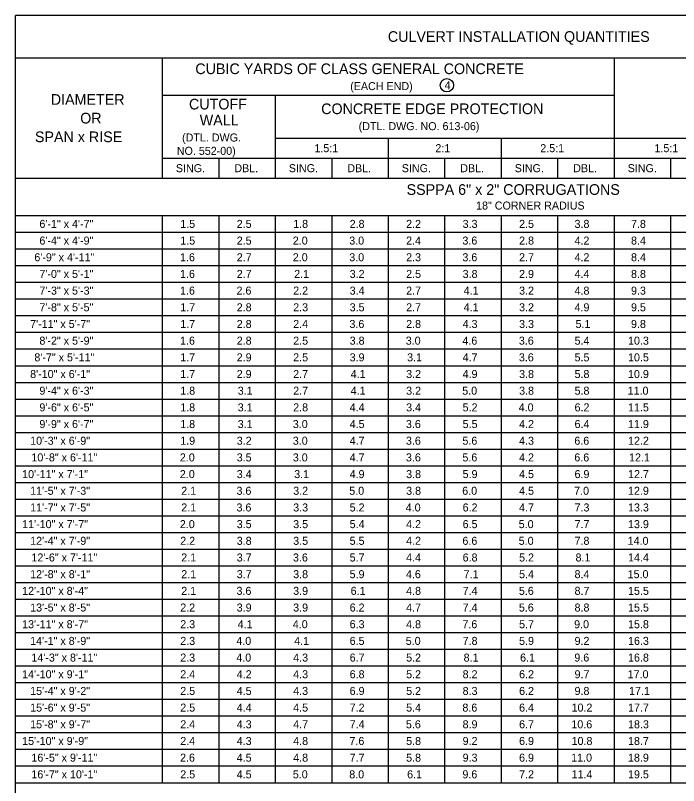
# Model space of a CAD drawing. Extents: x 49991.4 to 50047.6, y 49987.6 to 50011.4.
# Drawn here: x 50031.01 to 50035.98, y 49992.39 to 49998.16 of the extents above; entities that cross this region are included whole.
import ezdxf

# ---------------------------------------------------------------- set-up
doc = ezdxf.new("R2010")
doc.units = 0
doc.layers.add('Level 2', color=7, linetype='Continuous')

msp = doc.modelspace()

# ---------------------------------------------------------------- linework, layer by layer
at = {"layer": 'Level 2'}
for p, q in [((50031.0121, 49989.1307), (50031.0121, 49998.1607)), ((50038.8821, 49998.1607), (50031.0121, 49998.1607)), ((50038.8821, 49997.8407), (50031.0121, 49997.8407)), ((50032.1125, 49997.8407), (50032.1125, 49996.9407)), ((50035.4973, 49997.8407), (50035.4973, 49996.9407)), ((50035.4973, 49997.5607), (50032.1125, 49997.5607)), ((50032.9587, 49997.5607), (50032.9587, 49996.9407)), ((50032.9587, 49997.2407), (50038.0359, 49997.2407)), ((50033.8049, 49997.2407), (50033.8049, 49996.9407)), ((50034.6511, 49997.2407), (50034.6511, 49996.9407)), ((50032.1125, 49997.0907), (50038.8821, 49997.0907)), ((50032.5356, 49997.0907), (50032.5356, 49996.9407)), ((50033.3818, 49997.0907), (50033.3818, 49996.9407)), ((50034.228, 49997.0907), (50034.228, 49996.9407)), ((50035.0742, 49997.0907), (50035.0742, 49996.9407)), ((50035.9204, 49997.0907), (50035.9204, 49996.9407)), ((50031.0121, 49996.9407), (50038.8821, 49996.9407)), ((50031.0121, 49996.6607), (50038.8821, 49996.6607)), ((50032.1125, 49996.6607), (50032.1125, 49992.4107)), ((50032.5356, 49996.6607), (50032.5356, 49992.4107)), ((50032.9587, 49996.6607), (50032.9587, 49992.4107)), ((50033.3818, 49996.6607), (50033.3818, 49992.4107)), ((50033.8049, 49996.6607), (50033.8049, 49992.4107)), ((50034.228, 49996.6607), (50034.228, 49992.4107)), ((50034.6511, 49996.6607), (50034.6511, 49992.4107)), ((50035.0742, 49996.6607), (50035.0742, 49992.4107)), ((50035.4973, 49996.6607), (50035.4973, 49992.4107)), ((50035.9204, 49996.6607), (50035.9204, 49992.4107)), ((50031.0121, 49996.5357), (50038.8821, 49996.5357)), ((50031.0121, 49996.4107), (50038.8821, 49996.4107)), ((50031.0121, 49996.2857), (50038.8821, 49996.2857)), ((50031.0121, 49996.1607), (50038.8821, 49996.1607)), ((50031.0121, 49996.0357), (50038.8821, 49996.0357)), ((50031.0121, 49995.9107), (50038.8821, 49995.9107)), ((50031.0121, 49995.7857), (50038.8821, 49995.7857)), ((50031.0121, 49995.6607), (50038.8821, 49995.6607)), ((50031.0121, 49995.5357), (50038.8821, 49995.5357)), ((50031.0121, 49995.4107), (50038.8821, 49995.4107)), ((50031.0121, 49995.2857), (50038.8821, 49995.2857)), ((50031.0121, 49995.1607), (50038.8821, 49995.1607)), ((50031.0121, 49995.0357), (50038.8821, 49995.0357)), ((50031.0121, 49994.9107), (50038.8821, 49994.9107)), ((50031.0121, 49994.7857), (50038.8821, 49994.7857)), ((50031.0121, 49994.6607), (50038.8821, 49994.6607)), ((50031.0121, 49994.5357), (50038.8821, 49994.5357)), ((50031.0121, 49994.4107), (50038.8821, 49994.4107)), ((50031.0121, 49994.2857), (50038.8821, 49994.2857)), ((50031.0121, 49994.1607), (50038.8821, 49994.1607)), ((50031.0121, 49994.0357), (50038.8821, 49994.0357)), ((50031.0121, 49993.9107), (50038.8821, 49993.9107)), ((50031.0121, 49993.7857), (50038.8821, 49993.7857)), ((50031.0121, 49993.6607), (50038.8821, 49993.6607)), ((50031.0121, 49993.5357), (50038.8821, 49993.5357)), ((50031.0121, 49993.4107), (50038.8821, 49993.4107)), ((50031.0121, 49993.2857), (50038.8821, 49993.2857)), ((50031.0121, 49993.1607), (50038.8821, 49993.1607)), ((50031.0121, 49993.0357), (50038.8821, 49993.0357)), ((50031.0121, 49992.9107), (50038.8821, 49992.9107)), ((50031.0121, 49992.7857), (50038.8821, 49992.7857)), ((50031.0121, 49992.6607), (50038.8821, 49992.6607)), ((50031.0121, 49992.5357), (50038.8821, 49992.5357)), ((50031.0121, 49992.4107), (50038.8821, 49992.4107))]:
    msp.add_line(p, q, dxfattribs=at)
msp.add_circle((50034.2447, 49997.637), 0.05, dxfattribs=at)

# ---------------------------------------------------------------- texts
for s, height, p in [('CULVERT INSTALLATION QUANTITIES', 0.08, (50033.8025, 49997.9622)), ('CUBIC YARDS OF CLASS GENERAL CONCRETE', 0.08, (50032.3602, 49997.7207)), ('(EACH END)', 0.06, (50033.5204, 49997.6007)), ('4', 0.06, (50034.2276, 49997.607)), ('DIAMETER', 0.08, (50031.2774, 49997.4907)), ('CUTOFF', 0.08, (50032.3126, 49997.4557)), ('CONCRETE EDGE PROTECTION', 0.08, (50033.303, 49997.4207)), ('OR', 0.08, (50031.4974, 49997.3507)), ('WALL', 0.08, (50032.393, 49997.3357)), ('(DTL. DWG. NO. 613-06)', 0.06, (50033.5835, 49997.3007)), ('SPAN x RISE', 0.08, (50031.1584, 49997.2107)), ('(DTL. DWG.', 0.06, (50032.2608, 49997.2157)), ('NO. 552-00)', 0.06, (50032.2212, 49997.1157)), ('1.5:1', 0.06, (50033.2521, 49997.1357)), ('2:1', 0.06, (50034.1583, 49997.1357)), ('2.5:1', 0.06, (50034.9445, 49997.1357)), ('1.5:1', 0.06, (50035.7997, 49997.1357)), ('SING.', 0.06, (50032.2142, 49996.9857)), ('DBL.', 0.06, (50032.6524, 49996.9857)), ('SING.', 0.06, (50033.0605, 49996.9857)), ('DBL.', 0.06, (50033.4986, 49996.9857)), ('SING.', 0.06, (50033.9067, 49996.9857)), ('DBL.', 0.06, (50034.3448, 49996.9857)), ('SING.', 0.06, (50034.7529, 49996.9857)), ('DBL.', 0.06, (50035.191, 49996.9857)), ('SING.', 0.06, (50035.5991, 49996.9857)), ('SSPPA 6" x 2" CORRUGATIONS', 0.08, (50033.9427, 49996.8157)), ('18" CORNER RADIUS', 0.06, (50034.4635, 49996.7057)), ('6\'-1" x 4\'-7"', 0.06, (50031.1919, 49996.5682)), ('1.5', 0.06, (50032.2471, 49996.5682)), ('2.5', 0.06, (50032.6702, 49996.5682)), ('1.8', 0.06, (50033.0933, 49996.5682)), ('2.8', 0.06, (50033.5163, 49996.5682)), ('2.2', 0.06, (50033.9394, 49996.5682)), ('3.3', 0.06, (50034.3626, 49996.5682)), ('2.5', 0.06, (50034.7857, 49996.5682)), (' 3.8', 0.06, (50035.1788, 49996.5682)), (' 7.8', 0.06, (50035.6018, 49996.5682)), ('6\'-4" x 4\'-9"', 0.06, (50031.1919, 49996.4432)), ('1.5', 0.06, (50032.2471, 49996.4432)), ('2.5', 0.06, (50032.6702, 49996.4432)), ('2.0', 0.06, (50033.0903, 49996.4432)), ('3.0', 0.06, (50033.5133, 49996.4432)), ('2.4', 0.06, (50033.9394, 49996.4432)), ('3.6', 0.06, (50034.361, 49996.4432)), ('2.8', 0.06, (50034.7857, 49996.4432)), (' 4.2', 0.06, (50035.1788, 49996.4432)), (' 8.4', 0.06, (50035.6018, 49996.4432)), (' 6\'-9" x 4\'-11"', 0.06, (50031.1319, 49996.3182)), ('1.6', 0.06, (50032.2455, 49996.3182)), ('2.7', 0.06, (50032.6702, 49996.3182)), ('2.0', 0.06, (50033.0903, 49996.3182)), ('3.0', 0.06, (50033.5133, 49996.3182)), ('2.3', 0.06, (50033.9394, 49996.3182)), ('3.6', 0.06, (50034.361, 49996.3182)), ('2.7', 0.06, (50034.7857, 49996.3182)), (' 4.2', 0.06, (50035.1788, 49996.3182)), (' 8.4', 0.06, (50035.6018, 49996.3182)), ('7\'-0" x 5\'-1"', 0.06, (50031.1919, 49996.1932)), ('1.6', 0.06, (50032.2455, 49996.1932)), ('2.7', 0.06, (50032.6702, 49996.1932)), ('2.1', 0.06, (50033.1007, 49996.1932)), ('3.2', 0.06, (50033.5163, 49996.1932)), ('2.5', 0.06, (50033.9394, 49996.1932)), ('3.8', 0.06, (50034.3626, 49996.1932)), ('2.9', 0.06, (50034.7855, 49996.1932)), (' 4.4', 0.06, (50035.1788, 49996.1932)), (' 8.8', 0.06, (50035.6018, 49996.1932)), ('7\'-3" x 5\'-3"', 0.06, (50031.1919, 49996.0682)), ('1.6', 0.06, (50032.2455, 49996.0682)), ('2.6', 0.06, (50032.6686, 49996.0682)), ('2.2', 0.06, (50033.0933, 49996.0682)), ('3.4', 0.06, (50033.5163, 49996.0682)), ('2.7', 0.06, (50033.9394, 49996.0682)), ('4.1', 0.06, (50034.37, 49996.0682)), ('3.2', 0.06, (50034.7857, 49996.0682)), (' 4.8', 0.06, (50035.1788, 49996.0682)), (' 9.3', 0.06, (50035.6018, 49996.0682)), ('7\'-8" x 5\'-5"', 0.06, (50031.1919, 49995.9432)), ('1.7', 0.06, (50032.2471, 49995.9432)), ('2.8', 0.06, (50032.6702, 49995.9432)), ('2.3', 0.06, (50033.0933, 49995.9432)), ('3.5', 0.06, (50033.5163, 49995.9432)), ('2.7', 0.06, (50033.9394, 49995.9432)), ('4.1', 0.06, (50034.37, 49995.9432)), ('3.2', 0.06, (50034.7857, 49995.9432)), (' 4.9', 0.06, (50035.1786, 49995.9432)), (' 9.5', 0.06, (50035.6018, 49995.9432)), ('7\'-11" x 5\'-7" ', 0.06, (50031.1225, 49995.8182)), ('1.7', 0.06, (50032.2471, 49995.8182)), ('2.8', 0.06, (50032.6702, 49995.8182)), ('2.4', 0.06, (50033.0933, 49995.8182)), ('3.6', 0.06, (50033.5147, 49995.8182)), ('2.8', 0.06, (50033.9394, 49995.8182)), ('4.3', 0.06, (50034.3626, 49995.8182)), ('3.3', 0.06, (50034.7857, 49995.8182)), (' 5.1', 0.06, (50035.1862, 49995.8182)), (' 9.8', 0.06, (50035.6018, 49995.8182)), ('8\'-2" x 5\'-9"', 0.06, (50031.1919, 49995.6932)), ('1.6', 0.06, (50032.2455, 49995.6932)), ('2.8', 0.06, (50032.6702, 49995.6932)), ('2.5', 0.06, (50033.0933, 49995.6932)), ('3.8', 0.06, (50033.5163, 49995.6932)), ('3.0', 0.06, (50033.9364, 49995.6932)), ('4.6', 0.06, (50034.361, 49995.6932)), ('3.6', 0.06, (50034.7841, 49995.6932)), (' 5.4', 0.06, (50035.1788, 49995.6932)), ('10.3', 0.06, (50035.6018, 49995.6932)), (' 8\'-7" x 5\'-11"', 0.06, (50031.1319, 49995.5682)), ('1.7', 0.06, (50032.2471, 49995.5682)), ('2.9', 0.06, (50032.67, 49995.5682)), ('2.5', 0.06, (50033.0933, 49995.5682)), ('3.9', 0.06, (50033.5161, 49995.5682)), ('3.1', 0.06, (50033.9468, 49995.5682)), ('4.7', 0.06, (50034.3626, 49995.5682)), ('3.6', 0.06, (50034.7841, 49995.5682)), (' 5.5', 0.06, (50035.1788, 49995.5682)), ('10.5', 0.06, (50035.6018, 49995.5682)), ('8\'-10" x 6\'-1" ', 0.06, (50031.1225, 49995.4432)), ('1.7', 0.06, (50032.2471, 49995.4432)), ('2.9', 0.06, (50032.67, 49995.4432)), ('2.7', 0.06, (50033.0933, 49995.4432)), ('4.1', 0.06, (50033.5237, 49995.4432)), ('3.2', 0.06, (50033.9394, 49995.4432)), ('4.9', 0.06, (50034.3624, 49995.4432)), ('3.8', 0.06, (50034.7857, 49995.4432)), (' 5.8', 0.06, (50035.1788, 49995.4432)), ('10.9', 0.06, (50035.6016, 49995.4432)), ('9\'-4" x 6\'-3"', 0.06, (50031.1919, 49995.3182)), ('1.8', 0.06, (50032.2471, 49995.3182)), ('3.1', 0.06, (50032.6776, 49995.3182)), ('2.7', 0.06, (50033.0933, 49995.3182)), ('4.1', 0.06, (50033.5237, 49995.3182)), ('3.2', 0.06, (50033.9394, 49995.3182)), ('5.0', 0.06, (50034.3596, 49995.3182)), ('3.8', 0.06, (50034.7857, 49995.3182)), (' 5.8', 0.06, (50035.1788, 49995.3182)), ('11.0', 0.06, (50035.5988, 49995.3182)), ('9\'-6" x 6\'-5"', 0.06, (50031.1919, 49995.1932)), ('1.8', 0.06, (50032.2471, 49995.1932)), ('3.1', 0.06, (50032.6776, 49995.1932)), ('2.8', 0.06, (50033.0933, 49995.1932)), ('4.4', 0.06, (50033.5163, 49995.1932)), ('3.4', 0.06, (50033.9394, 49995.1932)), ('5.2', 0.06, (50034.3626, 49995.1932)), ('4.0', 0.06, (50034.7827, 49995.1932)), (' 6.2', 0.06, (50035.1788, 49995.1932)), ('11.5', 0.06, (50035.6018, 49995.1932)), ('9\'-9" x 6\'-7"', 0.06, (50031.1919, 49995.0682)), ('1.8', 0.06, (50032.2471, 49995.0682)), ('3.1', 0.06, (50032.6776, 49995.0682)), ('3.0', 0.06, (50033.0903, 49995.0682)), ('4.5', 0.06, (50033.5163, 49995.0682)), ('3.6', 0.06, (50033.9378, 49995.0682)), ('5.5', 0.06, (50034.3626, 49995.0682)), ('4.2', 0.06, (50034.7857, 49995.0682)), (' 6.4', 0.06, (50035.1788, 49995.0682)), ('11.9', 0.06, (50035.6016, 49995.0682)), ('10\'-3" x 6\'-9" ', 0.06, (50031.1225, 49994.9432)), ('1.9', 0.06, (50032.2469, 49994.9432)), ('3.2', 0.06, (50032.6702, 49994.9432)), ('3.0', 0.06, (50033.0903, 49994.9432)), ('4.7', 0.06, (50033.5163, 49994.9432)), ('3.6', 0.06, (50033.9378, 49994.9432)), ('5.6', 0.06, (50034.361, 49994.9432)), ('4.3', 0.06, (50034.7857, 49994.9432)), (' 6.6', 0.06, (50035.1772, 49994.9432)), ('12.2', 0.06, (50035.6018, 49994.9432)), ('10\'-8" x 6\'-11"', 0.06, (50031.1319, 49994.8182)), ('2.0', 0.06, (50032.2441, 49994.8182)), ('3.5', 0.06, (50032.6702, 49994.8182)), ('3.0', 0.06, (50033.0903, 49994.8182)), ('4.7', 0.06, (50033.5163, 49994.8182)), ('3.6', 0.06, (50033.9378, 49994.8182)), ('5.6', 0.06, (50034.361, 49994.8182)), ('4.2', 0.06, (50034.7857, 49994.8182)), (' 6.6', 0.06, (50035.1772, 49994.8182)), ('12.1', 0.06, (50035.6092, 49994.8182)), ('10\'-11" x 7\'-1"  ', 0.06, (50031.0625, 49994.6932)), ('2.0', 0.06, (50032.2441, 49994.6932)), ('3.4', 0.06, (50032.6702, 49994.6932)), ('3.1', 0.06, (50033.1007, 49994.6932)), ('4.9', 0.06, (50033.5161, 49994.6932)), ('3.8', 0.06, (50033.9394, 49994.6932)), ('5.9', 0.06, (50034.3624, 49994.6932)), ('4.5', 0.06, (50034.7857, 49994.6932)), (' 6.9', 0.06, (50035.1786, 49994.6932)), ('12.7', 0.06, (50035.6018, 49994.6932)), ('11\'-5" x 7\'-3" ', 0.06, (50031.1225, 49994.5682)), ('2.1', 0.06, (50032.2545, 49994.5682)), ('3.6', 0.06, (50032.6686, 49994.5682)), ('3.2', 0.06, (50033.0933, 49994.5682)), ('5.0', 0.06, (50033.5133, 49994.5682)), ('3.8', 0.06, (50033.9394, 49994.5682)), ('6.0', 0.06, (50034.3596, 49994.5682)), ('4.5', 0.06, (50034.7857, 49994.5682)), (' 7.0', 0.06, (50035.1758, 49994.5682)), ('12.9', 0.06, (50035.6016, 49994.5682)), ('11\'-7" x 7\'-5" ', 0.06, (50031.1225, 49994.4432)), ('2.1', 0.06, (50032.2545, 49994.4432)), ('3.6', 0.06, (50032.6686, 49994.4432)), ('3.3', 0.06, (50033.0933, 49994.4432)), ('5.2', 0.06, (50033.5163, 49994.4432)), ('4.0', 0.06, (50033.9364, 49994.4432)), ('6.2', 0.06, (50034.3626, 49994.4432)), ('4.7', 0.06, (50034.7857, 49994.4432)), (' 7.3', 0.06, (50035.1788, 49994.4432)), ('13.3', 0.06, (50035.6018, 49994.4432)), ('11\'-10" x 7\'-7"  ', 0.06, (50031.0625, 49994.3182)), ('2.0', 0.06, (50032.2441, 49994.3182)), ('3.5', 0.06, (50032.6702, 49994.3182)), ('3.5', 0.06, (50033.0933, 49994.3182)), ('5.4', 0.06, (50033.5163, 49994.3182)), ('4.2', 0.06, (50033.9394, 49994.3182)), ('6.5', 0.06, (50034.3626, 49994.3182)), ('5.0', 0.06, (50034.7827, 49994.3182)), (' 7.7', 0.06, (50035.1788, 49994.3182)), ('13.9', 0.06, (50035.6016, 49994.3182)), ('12\'-4" x 7\'-9" ', 0.06, (50031.1225, 49994.1932)), ('2.2', 0.06, (50032.2471, 49994.1932)), ('3.8', 0.06, (50032.6702, 49994.1932)), ('3.5', 0.06, (50033.0933, 49994.1932)), ('5.5', 0.06, (50033.5163, 49994.1932)), ('4.2', 0.06, (50033.9394, 49994.1932)), ('6.6', 0.06, (50034.361, 49994.1932)), ('5.0', 0.06, (50034.7827, 49994.1932)), (' 7.8', 0.06, (50035.1788, 49994.1932)), ('14.0', 0.06, (50035.5988, 49994.1932)), ('12\'-6" x 7\'-11"', 0.06, (50031.1319, 49994.0682)), ('2.1', 0.06, (50032.2545, 49994.0682)), ('3.7', 0.06, (50032.6702, 49994.0682)), ('3.6', 0.06, (50033.0917, 49994.0682)), ('5.7', 0.06, (50033.5163, 49994.0682)), ('4.4', 0.06, (50033.9394, 49994.0682)), ('6.8', 0.06, (50034.3626, 49994.0682)), ('5.2', 0.06, (50034.7857, 49994.0682)), (' 8.1', 0.06, (50035.1862, 49994.0682)), ('14.4', 0.06, (50035.6018, 49994.0682)), ('12\'-8" x 8\'-1" ', 0.06, (50031.1225, 49993.9432)), ('2.1', 0.06, (50032.2545, 49993.9432)), ('3.7', 0.06, (50032.6702, 49993.9432)), ('3.8', 0.06, (50033.0933, 49993.9432)), ('5.9', 0.06, (50033.5161, 49993.9432)), ('4.6', 0.06, (50033.9378, 49993.9432)), ('7.1', 0.06, (50034.37, 49993.9432)), ('5.4', 0.06, (50034.7857, 49993.9432)), (' 8.4', 0.06, (50035.1788, 49993.9432)), ('15.0', 0.06, (50035.5988, 49993.9432)), ('12\'-10" x 8\'-4"  ', 0.06, (50031.0625, 49993.8182)), ('2.1', 0.06, (50032.2545, 49993.8182)), ('3.6', 0.06, (50032.6686, 49993.8182)), ('3.9', 0.06, (50033.0931, 49993.8182)), ('6.1', 0.06, (50033.5237, 49993.8182)), ('4.8', 0.06, (50033.9394, 49993.8182)), ('7.4', 0.06, (50034.3626, 49993.8182)), ('5.6', 0.06, (50034.7841, 49993.8182)), (' 8.7', 0.06, (50035.1788, 49993.8182)), ('15.5', 0.06, (50035.6018, 49993.8182)), ('13\'-5" x 8\'-5" ', 0.06, (50031.1225, 49993.6932)), ('2.2', 0.06, (50032.2471, 49993.6932)), ('3.9', 0.06, (50032.67, 49993.6932)), ('3.9', 0.06, (50033.0931, 49993.6932)), ('6.2', 0.06, (50033.5163, 49993.6932)), ('4.7', 0.06, (50033.9394, 49993.6932)), ('7.4', 0.06, (50034.3626, 49993.6932)), ('5.6', 0.06, (50034.7841, 49993.6932)), (' 8.8', 0.06, (50035.1788, 49993.6932)), ('15.5', 0.06, (50035.6018, 49993.6932)), ('13\'-11" x 8\'-7"  ', 0.06, (50031.0625, 49993.5682)), ('2.3', 0.06, (50032.2471, 49993.5682)), ('4.1', 0.06, (50032.6776, 49993.5682)), ('4.0', 0.06, (50033.0903, 49993.5682)), ('6.3', 0.06, (50033.5163, 49993.5682)), ('4.8', 0.06, (50033.9394, 49993.5682)), ('7.6', 0.06, (50034.361, 49993.5682)), ('5.7', 0.06, (50034.7857, 49993.5682)), (' 9.0', 0.06, (50035.1758, 49993.5682)), ('15.8', 0.06, (50035.6018, 49993.5682)), ('14\'-1" x 8\'-9" ', 0.06, (50031.1225, 49993.4432)), ('2.3', 0.06, (50032.2471, 49993.4432)), ('4.0', 0.06, (50032.6672, 49993.4432)), ('4.1', 0.06, (50033.1007, 49993.4432)), ('6.5', 0.06, (50033.5163, 49993.4432)), ('5.0', 0.06, (50033.9364, 49993.4432)), ('7.8', 0.06, (50034.3626, 49993.4432)), ('5.9', 0.06, (50034.7855, 49993.4432)), (' 9.2', 0.06, (50035.1788, 49993.4432)), ('16.3', 0.06, (50035.6018, 49993.4432)), ('14\'-3" x 8\'-11"', 0.06, (50031.1319, 49993.3182)), ('2.3', 0.06, (50032.2471, 49993.3182)), ('4.0', 0.06, (50032.6672, 49993.3182)), ('4.3', 0.06, (50033.0933, 49993.3182)), ('6.7', 0.06, (50033.5163, 49993.3182)), ('5.2', 0.06, (50033.9394, 49993.3182)), ('8.1', 0.06, (50034.37, 49993.3182)), ('6.1', 0.06, (50034.7931, 49993.3182)), (' 9.6', 0.06, (50035.1772, 49993.3182)), ('16.8', 0.06, (50035.6018, 49993.3182)), ('14\'-10" x 9\'-1"  ', 0.06, (50031.0625, 49993.1932)), ('2.4', 0.06, (50032.2471, 49993.1932)), ('4.2', 0.06, (50032.6702, 49993.1932)), ('4.3', 0.06, (50033.0933, 49993.1932)), ('6.8', 0.06, (50033.5163, 49993.1932)), ('5.2', 0.06, (50033.9394, 49993.1932)), ('8.2', 0.06, (50034.3626, 49993.1932)), ('6.2', 0.06, (50034.7857, 49993.1932)), (' 9.7', 0.06, (50035.1788, 49993.1932)), ('17.0', 0.06, (50035.5988, 49993.1932)), ('15\'-4" x 9\'-2" ', 0.06, (50031.1225, 49993.0682)), ('2.5', 0.06, (50032.2471, 49993.0682)), ('4.5', 0.06, (50032.6702, 49993.0682)), ('4.3', 0.06, (50033.0933, 49993.0682)), ('6.9', 0.06, (50033.5161, 49993.0682)), ('5.2', 0.06, (50033.9394, 49993.0682)), ('8.3', 0.06, (50034.3626, 49993.0682)), ('6.2', 0.06, (50034.7857, 49993.0682)), (' 9.8', 0.06, (50035.1788, 49993.0682)), ('17.1', 0.06, (50035.6092, 49993.0682)), ('15\'-6" x 9\'-5" ', 0.06, (50031.1225, 49992.9432)), ('2.5', 0.06, (50032.2471, 49992.9432)), ('4.4', 0.06, (50032.6702, 49992.9432)), ('4.5', 0.06, (50033.0933, 49992.9432)), ('7.2', 0.06, (50033.5163, 49992.9432)), ('5.4', 0.06, (50033.9394, 49992.9432)), ('8.6', 0.06, (50034.361, 49992.9432)), ('6.4', 0.06, (50034.7857, 49992.9432)), ('10.2', 0.06, (50035.1788, 49992.9432)), ('17.7', 0.06, (50035.6018, 49992.9432)), ('15\'-8" x 9\'-7" ', 0.06, (50031.1225, 49992.8182)), ('2.4', 0.06, (50032.2471, 49992.8182)), ('4.3', 0.06, (50032.6702, 49992.8182)), ('4.7', 0.06, (50033.0933, 49992.8182)), ('7.4', 0.06, (50033.5163, 49992.8182)), ('5.6', 0.06, (50033.9378, 49992.8182)), ('8.9', 0.06, (50034.3624, 49992.8182)), ('6.7', 0.06, (50034.7857, 49992.8182)), ('10.6', 0.06, (50035.1772, 49992.8182)), ('18.3', 0.06, (50035.6018, 49992.8182)), ('15\'-10" x 9\'-9"  ', 0.06, (50031.0625, 49992.6932)), ('2.4', 0.06, (50032.2471, 49992.6932)), ('4.3', 0.06, (50032.6702, 49992.6932)), ('4.8', 0.06, (50033.0933, 49992.6932)), ('7.6', 0.06, (50033.5147, 49992.6932)), ('5.8', 0.06, (50033.9394, 49992.6932)), ('9.2', 0.06, (50034.3626, 49992.6932)), ('6.9', 0.06, (50034.7855, 49992.6932)), ('10.8', 0.06, (50035.1788, 49992.6932)), ('18.7', 0.06, (50035.6018, 49992.6932)), ('16\'-5" x 9\'-11"', 0.06, (50031.1319, 49992.5682)), ('2.6', 0.06, (50032.2455, 49992.5682)), ('4.5', 0.06, (50032.6702, 49992.5682)), ('4.8', 0.06, (50033.0933, 49992.5682)), ('7.7', 0.06, (50033.5163, 49992.5682)), ('5.8', 0.06, (50033.9394, 49992.5682)), ('9.3', 0.06, (50034.3626, 49992.5682)), ('6.9', 0.06, (50034.7855, 49992.5682)), ('11.0', 0.06, (50035.1758, 49992.5682)), ('18.9', 0.06, (50035.6016, 49992.5682)), ('16\'-7" x 10\'-1"', 0.06, (50031.1319, 49992.4432)), ('2.5', 0.06, (50032.2471, 49992.4432)), ('4.5', 0.06, (50032.6702, 49992.4432)), ('5.0', 0.06, (50033.0903, 49992.4432)), ('8.0', 0.06, (50033.5133, 49992.4432)), ('6.1', 0.06, (50033.9468, 49992.4432)), ('9.6', 0.06, (50034.361, 49992.4432)), ('7.2', 0.06, (50034.7857, 49992.4432)), ('11.4', 0.06, (50035.1788, 49992.4432)), ('19.5', 0.06, (50035.6018, 49992.4432))]:
    msp.add_text(s, height=height, dxfattribs=at).set_placement(p)

doc.saveas('drawing.dxf')
